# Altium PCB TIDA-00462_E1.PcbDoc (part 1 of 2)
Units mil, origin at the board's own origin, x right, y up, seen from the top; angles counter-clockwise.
Board outline 2300 x 2550 mil, 4 copper layers (Top Layer, MidLayer1 (GND), MidLayer2 (PWR), Bottom Layer), stack 79.8 mil thick; 106 components, 69 nets, 311 pads, 76 vias.
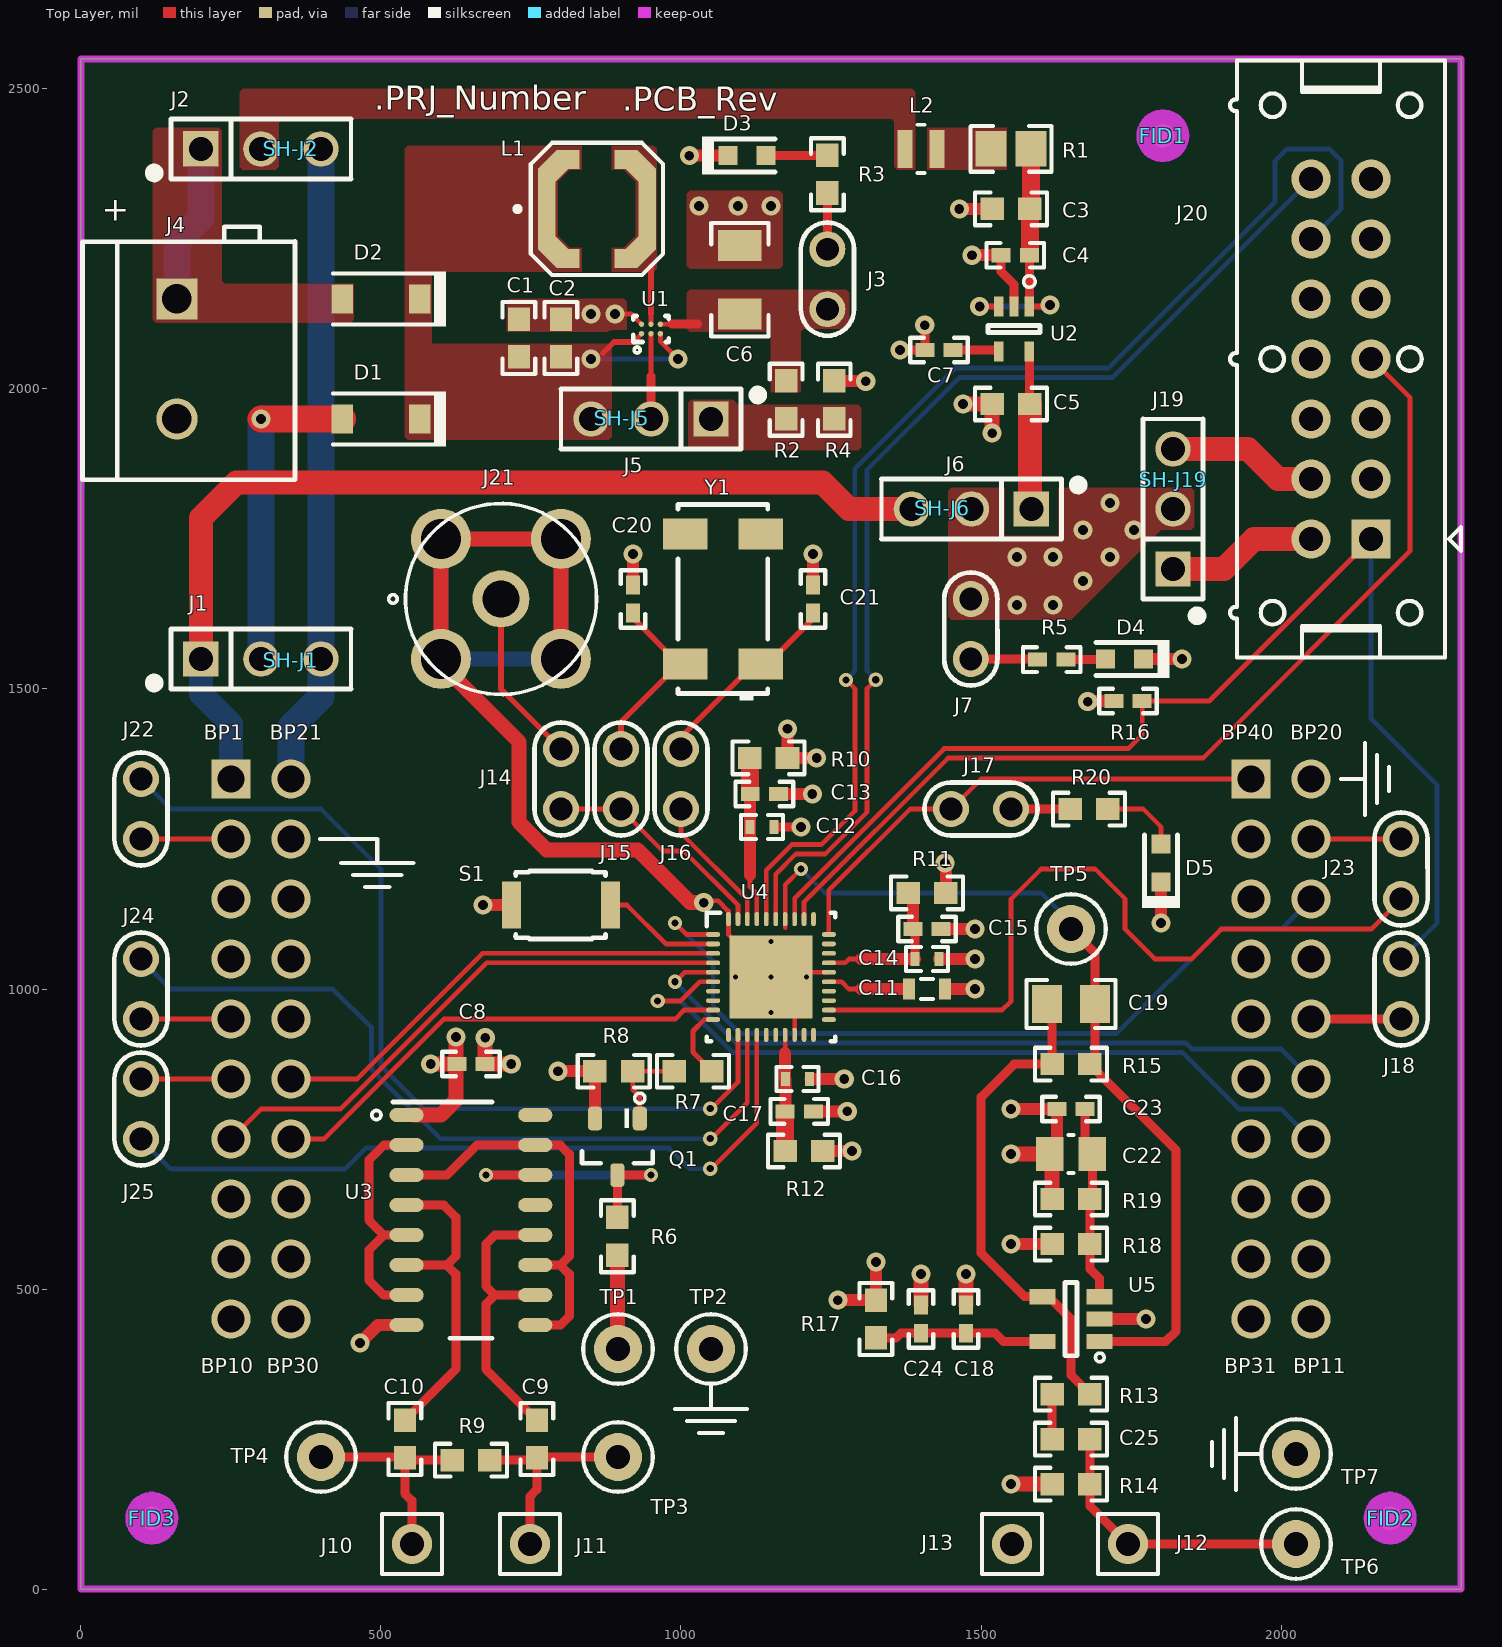
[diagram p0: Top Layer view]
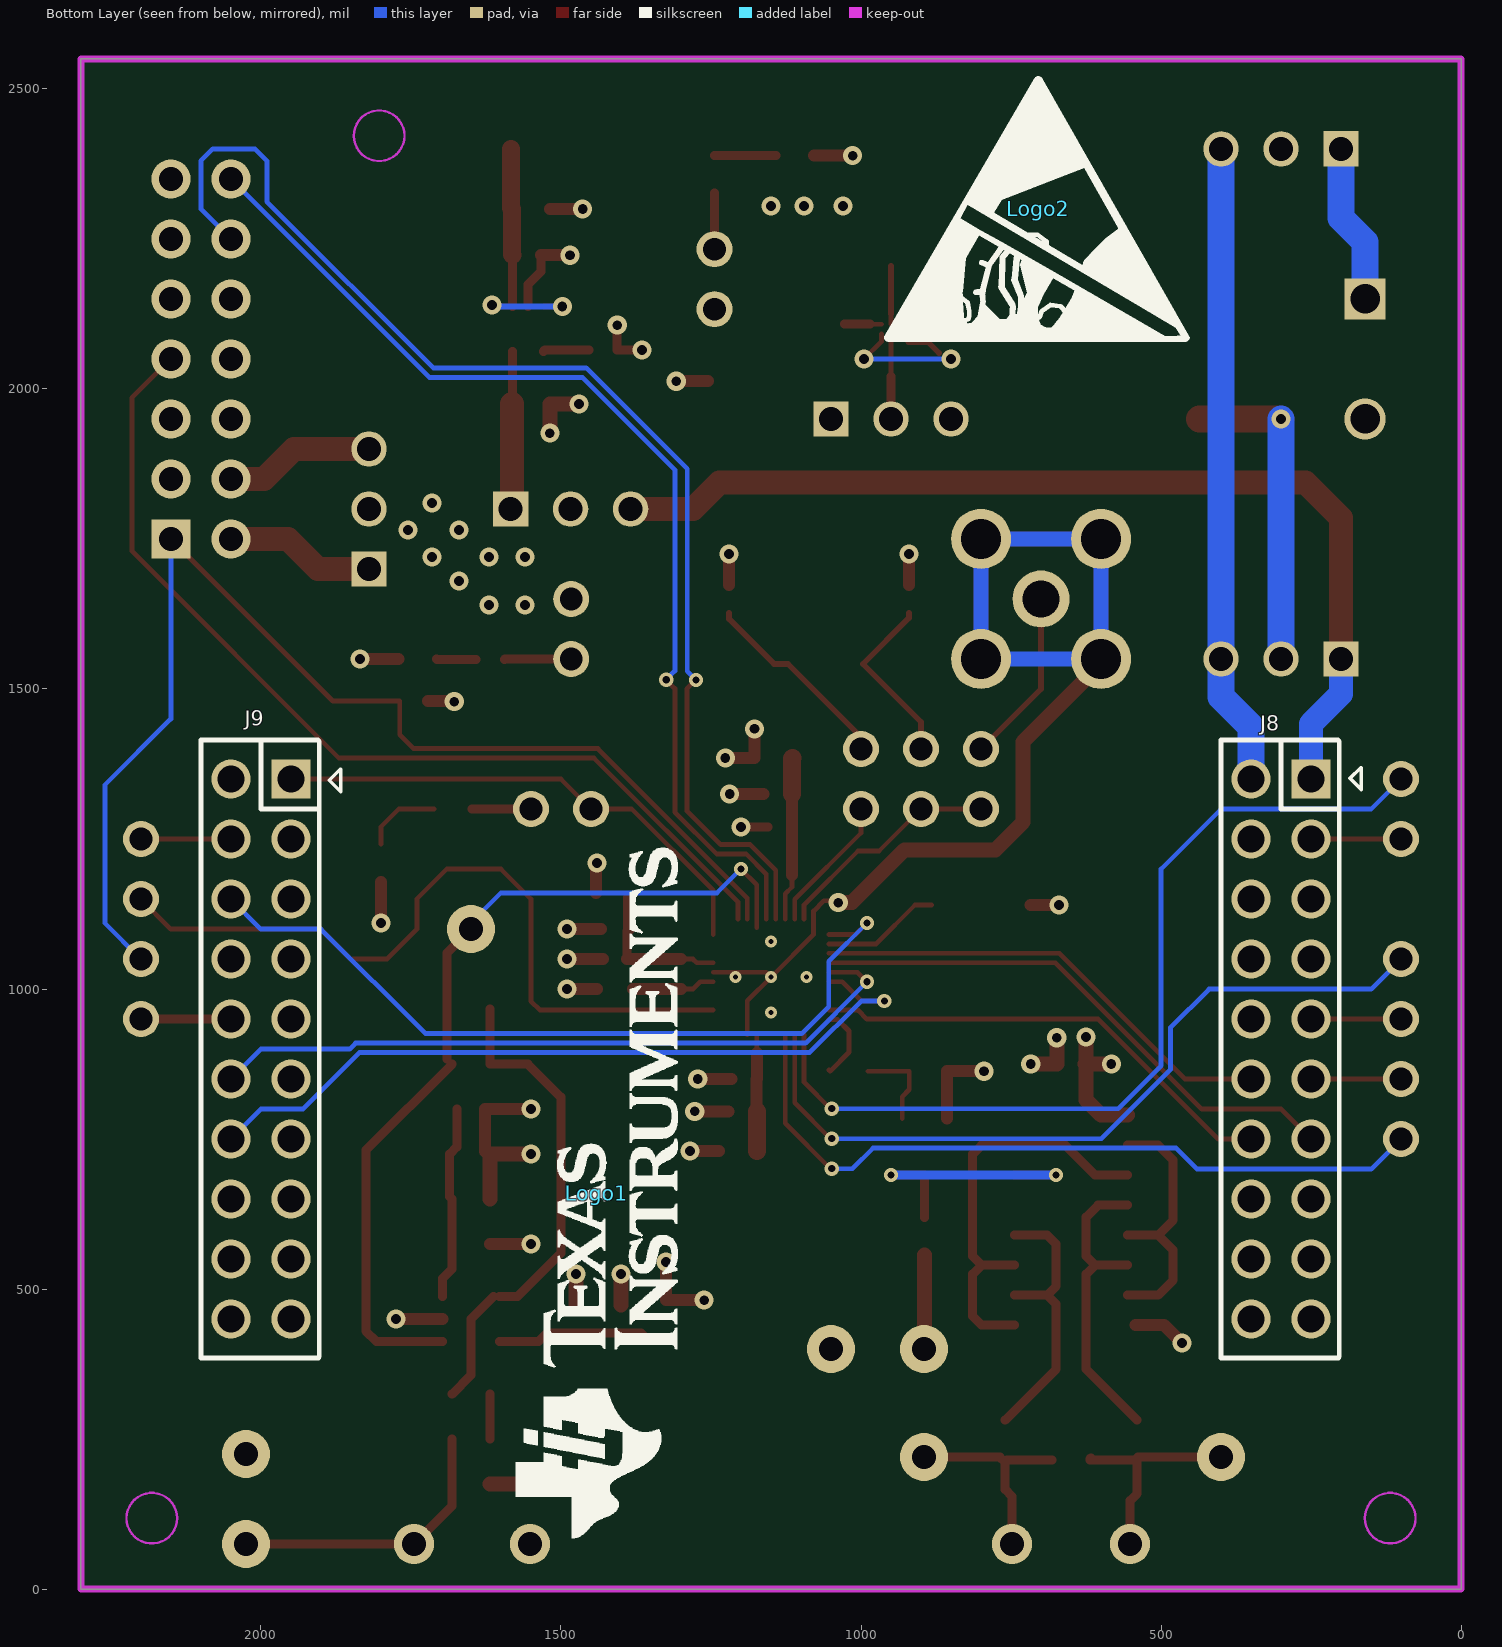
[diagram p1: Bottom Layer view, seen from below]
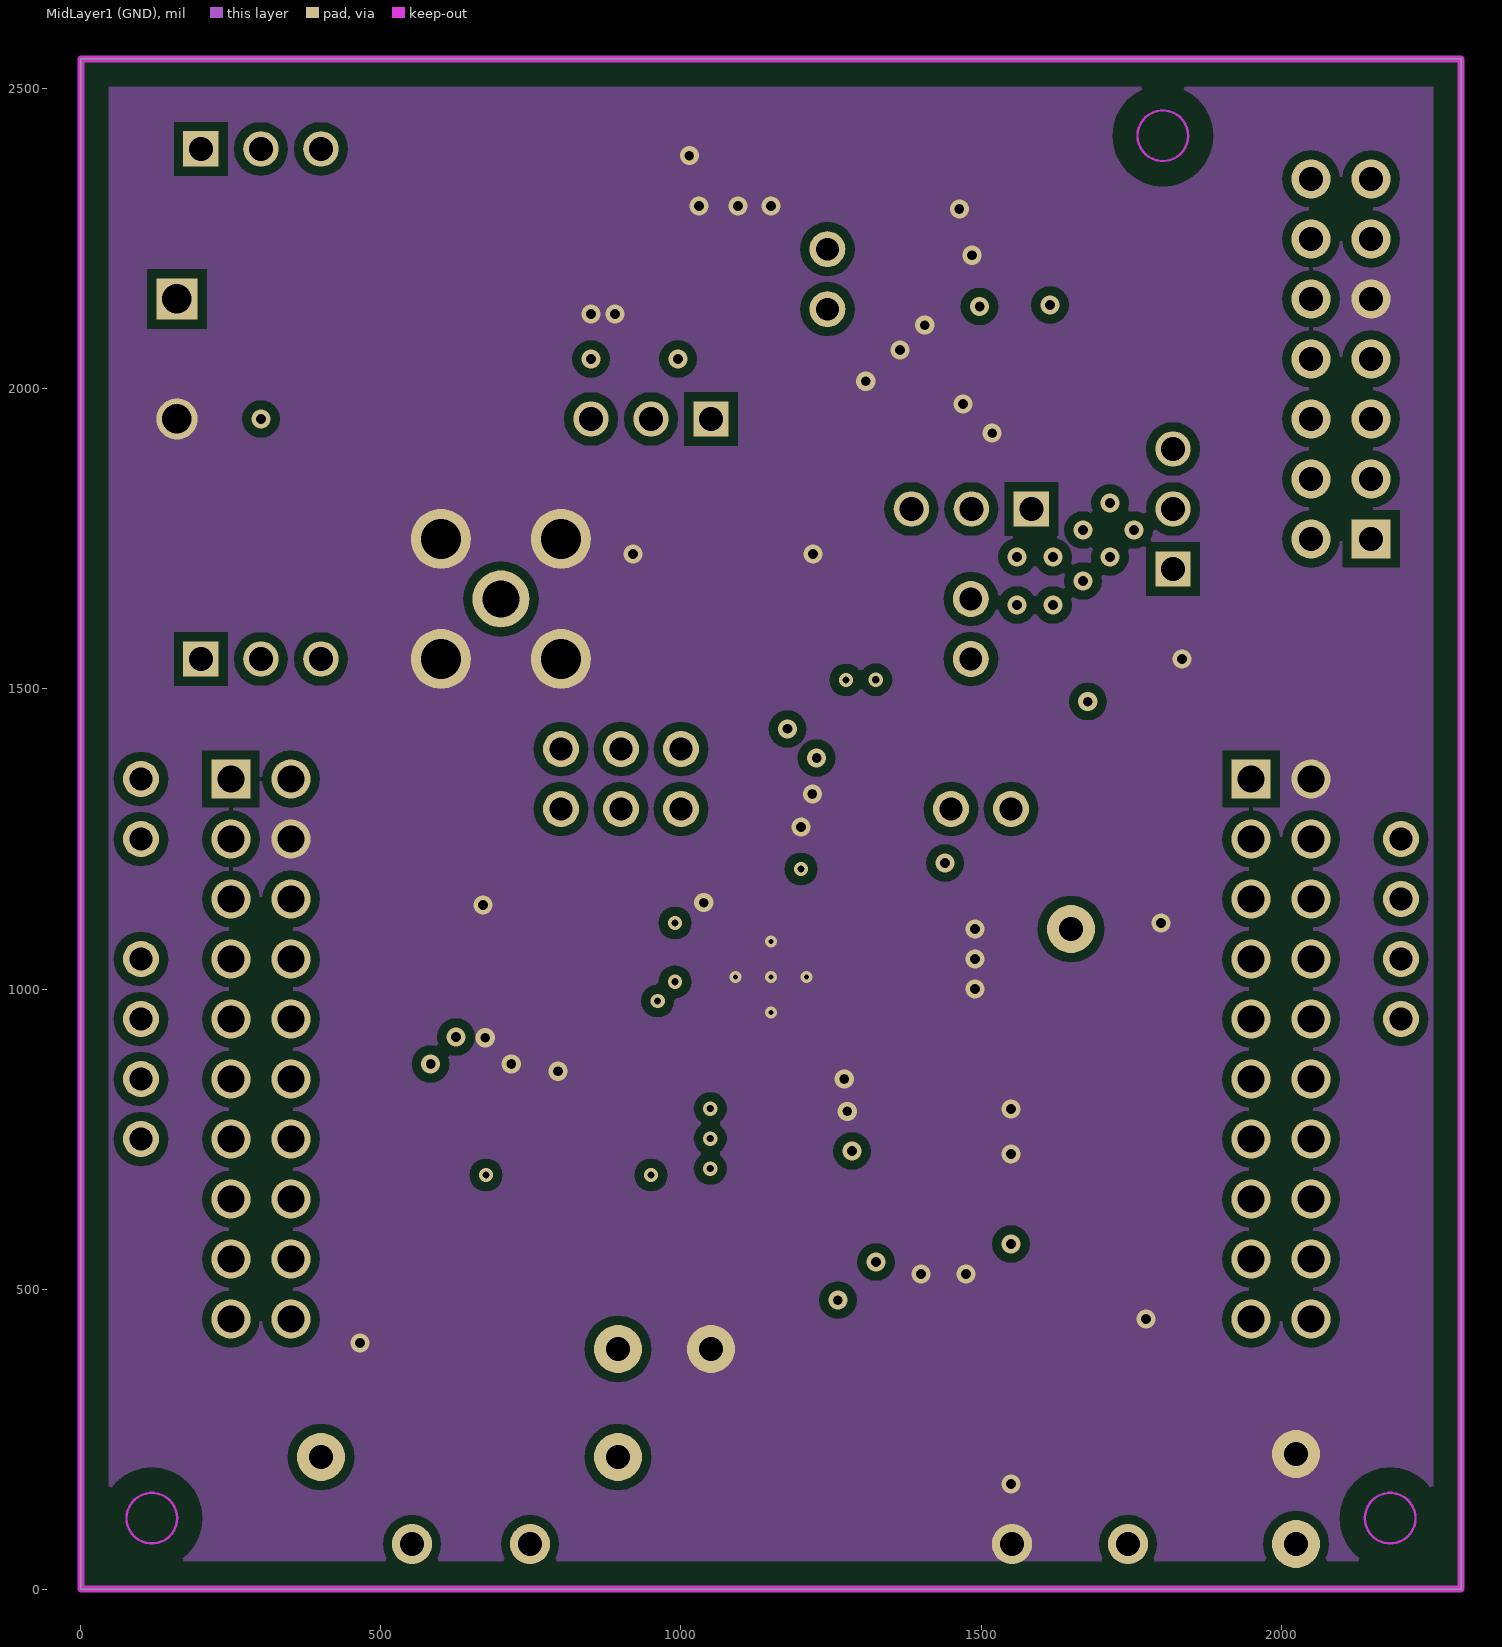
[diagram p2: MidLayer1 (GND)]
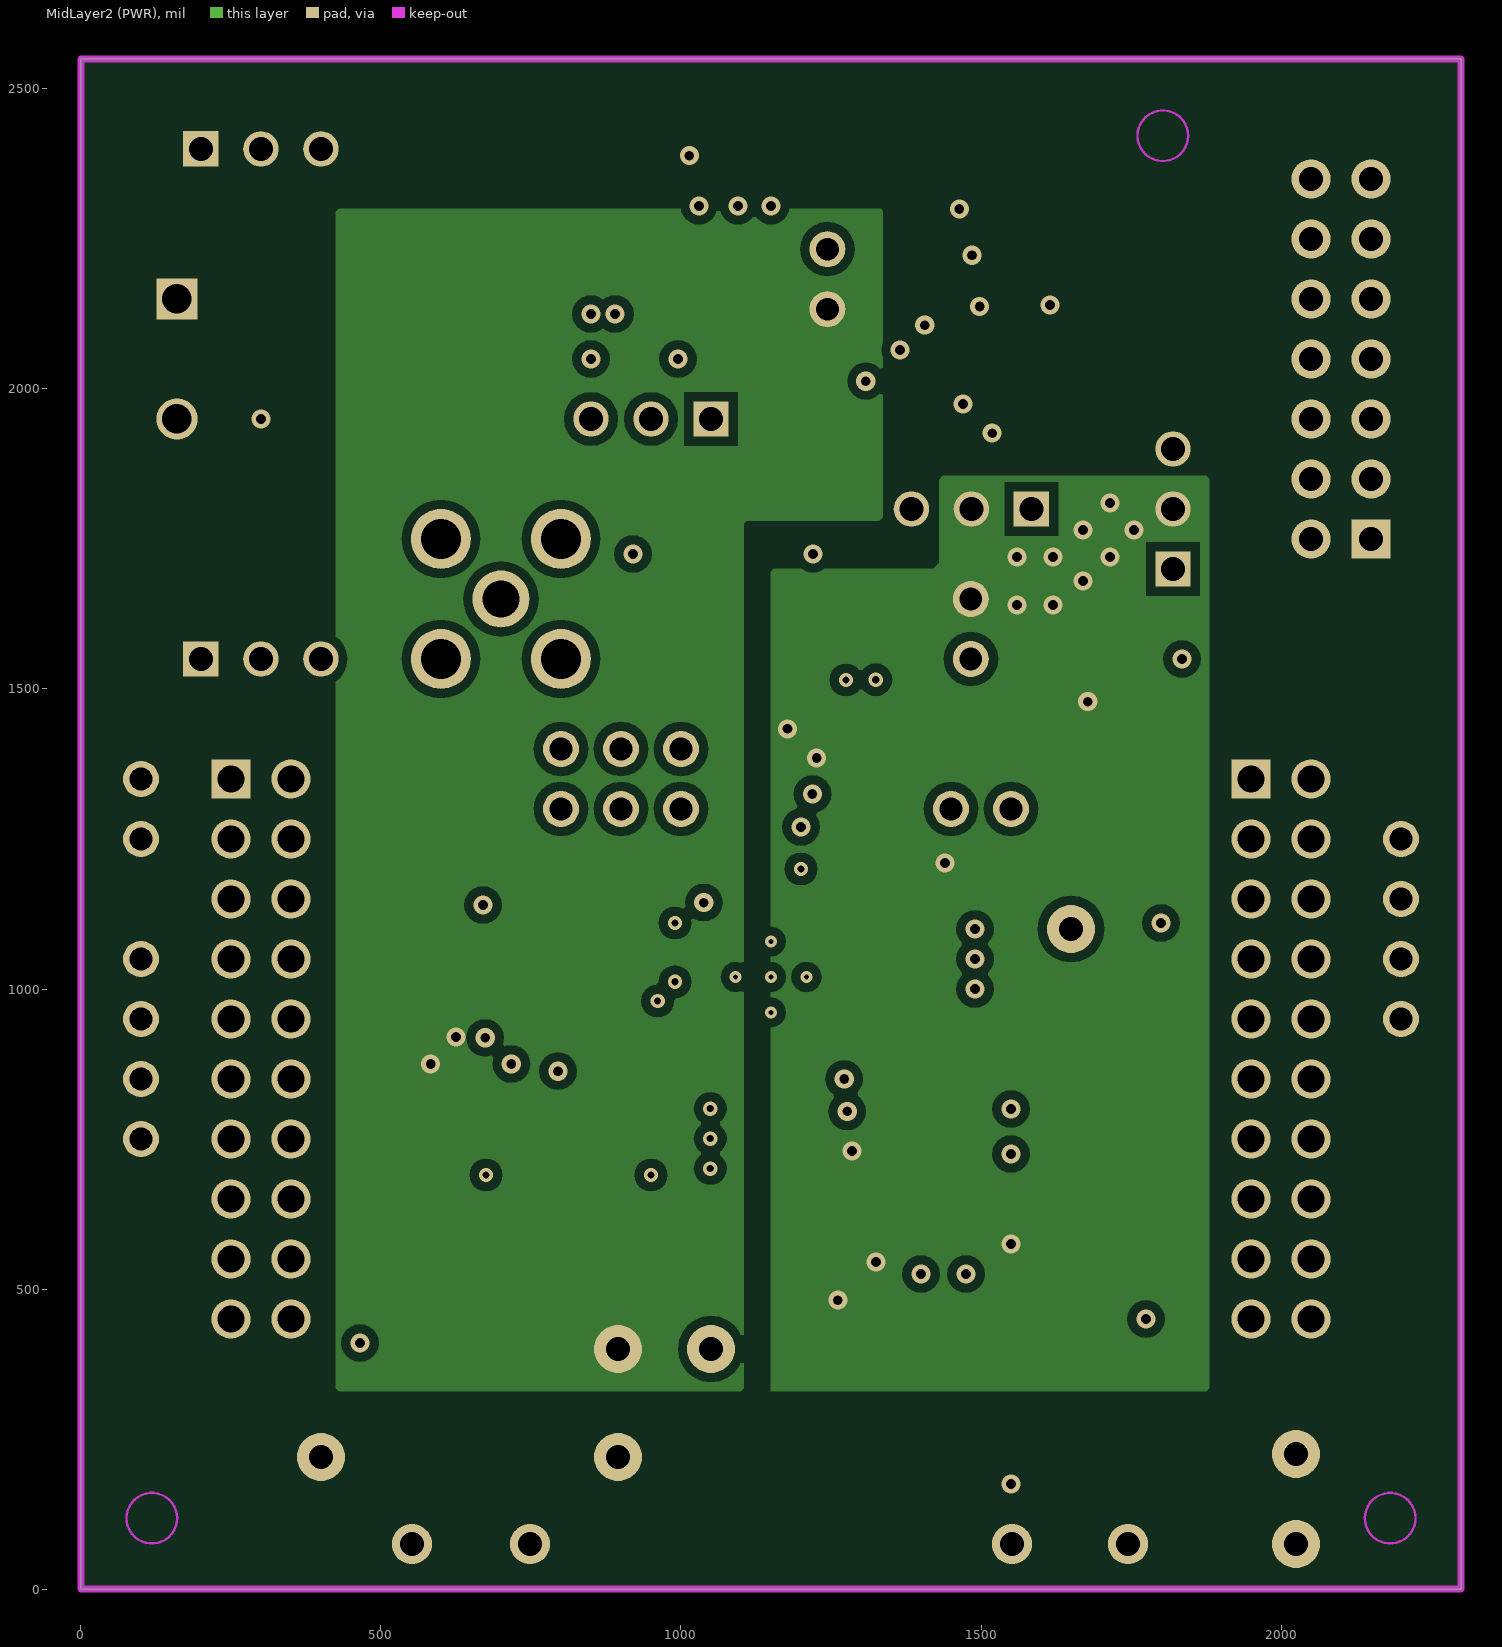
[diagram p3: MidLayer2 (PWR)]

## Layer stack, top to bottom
Top Solder: solder mask 0.4, Solder Resist, Dk 3.5
Top Layer: signal copper 1.4
Dielectric1: core 59.2, FR-4, Dk 4.8
MidLayer1 (GND): signal copper 1.4
Dielectric2: prepreg 5, Dk 4.2
MidLayer2 (PWR): signal copper 1.4
Dielectric3: core 10, Dk 4.2
Bottom Layer: signal copper 1.4
Bottom Solder: solder mask 0.4, Solder Resist, Dk 3.5

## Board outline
0,0 0,2550 2300,2550 2300,0 0,0

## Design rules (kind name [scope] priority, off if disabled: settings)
AcuteAngle [All] p1: minimum=4.50000000000000E+0001 checktracksonly=TRUE
AssemblyTestPointUsage [All] p1: valid=2
Clearance Clearance_U1 [InPadClass('u1_pad')] p1: gap=6.69
Clearance "Clearance_poly _poly" [InPolygon vs InPolygon] p2: gap=20
Clearance "VIA to SMD" [IsVia vs InAnyComponent] p3: gap=8
Clearance Clearance_BoardEdge_MountingHoles [OnCopper and InComponentClass('Mounting Holes') vs IsKeepOut] p4: gap=40
Clearance Clearance_BoardEdge_Poly [OnCopper and InPoly vs IsKeepOut] p5: gap=40
Clearance Clearance_Poly [InPolygon] p6: gap=15
Clearance [All] p7: gap=7.87
ComponentClearance ComponentClearance_MountingHoles_FiducialMarks [InComponentClass('Mounting Holes') vs InComponentClass('FiducialMark')] p1: gap=40 collisioncheckmode=3 verticalgap=10 showdistances=FALSE
ComponentClearance ComponentClearance_Shunt [InComponentClass('Header') vs InComponentClass('Shunt')] p2: gap=0 collisioncheckmode=3 verticalgap=0 showdistances=FALSE
ComponentClearance ComponentClearance_Logo [InComponentClass('Logo')] p3: gap=35 collisioncheckmode=3 verticalgap=10 showdistances=FALSE
ComponentClearance ComponentClearance_ScrewToNut [(HasFootprint('NY PMS 440 0025 PH')) vs (HasFootprint('Keystone_1902C'))] p4: gap=5 collisioncheckmode=3 verticalgap=10 showdistances=FALSE
ComponentClearance ComponentClearance_MountingHoles [InComponentClass('Mounting Holes')] p5: gap=250 collisioncheckmode=3 verticalgap=100000 showdistances=FALSE
ComponentClearance ComponentClearance_SmallPassives [HasFootprint('0201*') or HasFootprint('0402*') or HasFootprint('0508') or HasFootprint('0603*') or HasFootprint('0612') or HasFootprint('0805*') or HasFootprint('0815*') or HasFootprint('0830*') or HasFootprint('1206*') or HasFootprint('1210*') or HasFootprint('1808*') or HasFootprint('1812*') or HasFootprint('1825*') or HasFootprint('2010*') or HasFootprint('2220*') or HasFootprint('2225*') or HasFootprint('2512*') or HasFootprint('2728*') or HasFootprint('3518*') vs HasFootprint('0201*') or HasFootprint('0402*') or HasFootprint('0508') or HasFootprint('0603*') or HasFootprint('0612') or HasFootprint('0805*') or HasFootprint('0815*') or HasFootprint('0830*') or HasFootprint('1206*') or HasFootprint('1210*') or HasFootprint('1808*') or HasFootprint('1812*') or HasFootprint('1825*') or HasFootprint('2010*') or HasFootprint('2220*') or HasFootprint('2225*') or HasFootprint('2512*') or HasFootprint('2728*') or HasFootprint('3518*')] p6: gap=20 collisioncheckmode=3 verticalgap=10 showdistances=FALSE
ComponentClearance ComponentClearance_THtoSMT [IsThruComponent vs IsSMTComponent] p7: gap=50 collisioncheckmode=3 verticalgap=30 showdistances=FALSE
ComponentClearance ComponentClearance_THtoTH [IsThruComponent vs IsThruComponent] p8: gap=118.11 collisioncheckmode=3 verticalgap=30 showdistances=FALSE
ComponentClearance [All] p9: gap=30 collisioncheckmode=3 verticalgap=10 showdistances=FALSE
DiffPairsRouting DiffPair_DP_DMDiffPairsRouting [InDifferentialPair ('MSP_DP_DM_DIFF')] p1: maxlimit=8 minlimit=8 mostfreqgap=8 toplayer_minwidth=15 toplayer_maxwidth=15 toplayer_prefwidth=15 midlayer1_minwidth=15 midlayer1_maxwidth=15 midlayer1_prefwidth=15 midlayer2_minwidth=15 midlayer2_maxwidth=15 midlayer2_prefwidth=15 bottomlayer_minwidth=15 bottomlayer_maxwidth=15 bottomlayer_prefwidth=15 maxuncoupledlength=500
DiffPairsRouting DiffPair_MSP_DP_DMDiffPairsRouting [InDifferentialPair ('MSP_DP_DM_DIFF')] p2: maxlimit=8 minlimit=8 mostfreqgap=8 toplayer_minwidth=15 toplayer_maxwidth=15 toplayer_prefwidth=15 midlayer1_minwidth=15 midlayer1_maxwidth=15 midlayer1_prefwidth=15 midlayer2_minwidth=15 midlayer2_maxwidth=15 midlayer2_prefwidth=15 bottomlayer_minwidth=15 bottomlayer_maxwidth=15 bottomlayer_prefwidth=15 maxuncoupledlength=500
DiffPairsRouting [All] p3: maxlimit=8 minlimit=8 mostfreqgap=8 toplayer_minwidth=15 toplayer_maxwidth=15 toplayer_prefwidth=15 midlayer1_minwidth=15 midlayer1_maxwidth=15 midlayer1_prefwidth=15 midlayer2_minwidth=15 midlayer2_maxwidth=15 midlayer2_prefwidth=15 bottomlayer_minwidth=15 bottomlayer_maxwidth=15 bottomlayer_prefwidth=15 maxuncoupledlength=1000
FabricationTestPointUsage TestPointUsage [All] p1: valid=2 allowmultiple=FALSE
FabricationTestpoint Testpoint [All] p1: side=3 testpointundercomponent=TRUE minsize=40 maxsize=100 preferedsize=60 minholesize=0 maxholesize=40 preferedholesize=32 testpointgrid=1 allowsidetop=TRUE allowsidebottom=TRUE usegrid=TRUE gridtolerance=0.01
FanoutControl Fanout_LCC [IsLCC] p1: bgadir=Out bgaviamode=Centered fanoutstyle=Auto fanoutdirection=Alternating viagrid=1 // Fanout_LCC (Default Rule)
FanoutControl Fanout_BGA [IsBGA] p2: bgadir=Out bgaviamode=Centered fanoutstyle=Auto fanoutdirection=Alternating viagrid=1 // Fanout_BGA (Default Rule)
FanoutControl Fanout_Default [All] p4: bgadir=Out bgaviamode=Centered fanoutstyle=Auto fanoutdirection=Alternating viagrid=1 // Fanout_Default (Default Rule)
FanoutControl Fanout_Small [(CompPinCount < 5)] p5: bgadir=Out bgaviamode=Centered fanoutstyle=Auto fanoutdirection=OutThenIn viagrid=1 // Fanout_Small (Default Rule)
HoleSize [All] p1: absolutevalues=TRUE maxlimit=251 minlimit=7.87 maxpercent=80.000 minpercent=20.000
MatchedLengths DiffPair_DP_DMMatchedLengths [InDifferentialPair ('MSP_DP_DM_DIFF')] p1: tolerance=200 checknetsindiffpair=TRUE checkdiffpairvsdiffpair=TRUE checkothers=TRUE
MatchedLengths DiffPair_MSP_DP_DMMatchedLengths [InDifferentialPair ('MSP_DP_DM_DIFF')] p2: tolerance=200 checknetsindiffpair=TRUE checkdiffpairvsdiffpair=TRUE checkothers=TRUE
MinimumAnnularRing MinimumAnnularRing_ThermalPadVias [IsVia and InAnyComponent] p1: minimumring=5.91
MinimumAnnularRing [All] p2: minimumring=6
MinimumSolderMaskSliver MinimumSolderMaskSliver_Logo [InComponentClass('Logo') vs InComponentClass('Logo')] p1: minsoldermaskwidth=0.7
MinimumSolderMaskSliver [All] p2: minsoldermaskwidth=2.5
PlaneConnect [All] p1: planeconnectstyle=Direct reliefexpansion=10 reliefentries=4 reliefconductorwidth=10 reliefairgap=10
PolygonConnect [All] p1: connectstyle=Direct reliefconductorwidth=10 reliefentries=4 polygonreliefangle="90 Angle" airgapwidth=10
RoutingVias RoutingVias_power [InNetClass('power')] p1: holewidth=16 width=32 viastyle="Through Hole" minholewidth=16 minwidth=32 maxholewidth=16 maxwidth=32
RoutingVias ThermalPadVias [IsVia and InAnyComponent] p2: holewidth=12 width=24 viastyle="Through Hole" minholewidth=7.87 minwidth=19.68 maxholewidth=16 maxwidth=32
RoutingVias [All] p3: holewidth=12 width=24 viastyle="Through Hole" minholewidth=12 minwidth=24 maxholewidth=12 maxwidth=24
SilkToSilkClearance SilkToSilkClearance_Pb-FreeLogo [(HasFootprint('Pb-Free_Overlay_Medium') OR HasFootprint('Pb-Free_Overlay_Small')) vs (HasFootprint('Pb-Free_Overlay_Medium') OR HasFootprint('Pb-Free_Overlay_Small'))] p1: silktosilkclearance=0
SilkToSilkClearance [All] p2: silktosilkclearance=5
SilkToSolderMaskClearance "Silk to Solder Mask Opening" [IsPad] p1: minsilkscreentomaskgap=1 clearancetoexposedcopper=TRUE
SolderMaskExpansion [All] p1: expansion=1.97
UnpouredPolygon [All] p1: allowunpoured=FALSE
Width Width_PWR [InNetClass('power')] p1: maxlimit=100 minlimit=7.87 preferedwidth=20
Width [All] p2: maxlimit=100 minlimit=7.87 preferedwidth=10 checkconnectedcopper=TRUE
15 further rules are at their usual default settings.

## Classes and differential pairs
pad class u1_pad: U1-A1 U1-A2 U1-B1 U1-B2 U1-C1 U1-C2
component class Shunt: SH-J1 SH-J2 SH-J5 SH-J6 SH-J19
component class Logo: Logo1
component class TIDA-00462_E1_TID_Hardware: FID1 FID2 FID3 Logo1 Logo2 ZZ1 ZZ2 ZZ3 ZZ4
component class FiducialMark: FID1 FID2 FID3
component class AssemblyNote: ZZ1 ZZ2 ZZ3 ZZ4
component class TIDA-00462_E1_Power_Supply: C1 C2 C3 C4 C5 C6 C7 D1 D2 D3 D4 J1 J2 J3 J4 J5 J6 J7 J8 J9 J18 J19 J20 J22 J23 J24 J25 L1 L2 R1 R2 R3 R4 R5 SH-J1 SH-J2 SH-J5 SH-J6 SH-J19 TP1 TP2 U1 U2
component class TIDA-00462_E1_MCU_US_TX_RX: C8 C9 C10 C11 C12 C13 C14 C15 C16 C17 C18 C19 C20 C21 C22 C23 C24 C25 D5 J10 J11 J12 J13 J14 J15 J16 J17 J21 Q1 R6 R7 R8 R9 R10 R11 R12 R13 R14 R15 R16 R17 R18 R19 R20 S1 TP3 TP4 TP5 TP6 TP7 U3 U4 U5 Y1

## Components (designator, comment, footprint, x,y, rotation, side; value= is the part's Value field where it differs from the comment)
C1 "C1608X7R1C105K" 0603 730,2085 r90 top
C2 "C0603C104M4RACTU" 0603 800,2085 r90 top
C3 "GRM188R71E105KA12D" 0603 1550,2300 r180 top
C4 "C1005X7R1H104K050BB" 0402 1557,2223 r180 top
C5 "GRM188R71E105KA12D" 0603 1550,1975 r180 top
C6 "GMK316AB7106KL" 1206 1098,2182 r90 top
C7 "C1005X7R1C103K" 0402 1430,2065 r180 top
C8 "C1005X7R1H104K050BB" 0402 650,875 r0 top
C9 "C1608X7R1H224K080AB" 0603 760,250 r90 top
C10 "C1608X7R1H224K080AB" 0603 540,250 r90 top
C11 "GRM188R70J474KA01D" 0603S 1410,1000 r0 top
C12 "GRM155R70J104KA01D" 0402S 1135,1270 r0 top
C13 "CL05A106MQ5NUNC" 0402 1139,1325 r0 top
C14 "GRM155R70J104KA01D" 0402S 1410,1050 r0 top
C15 "CL05A106MQ5NUNC" 0402 1410,1100 r0 top
C16 "GRM155R70J104KA01D" 0402S 1194,850 r0 top
C17 "CL05A106MQ5NUNC" 0402 1197,796 r0 top
C18 "C1005X7R1H104K050BB" 0402 1475,450 r90 top
C19 "CC0805DRNP09BN7R0" 0805_HV 1650,975 r0 top
C20 "C1005C0G1H220J050BA" 0402 920,1650 r90 top
C21 "C1005C0G1H220J050BA" 0402 1220,1650 r90 top
C22 "885012207026" 0805_145 1650,725 r180 top
C23 "C1005X7R1H104K050BB" 0402 1650,800 r180 top
C24 "CL05A106MQ5NUNC" 0402 1400,450 r90 top
C25 "GRM188R71C103KA01D" 0603 1650,250 r180 top
D1 "MBR0540T1G" SOD-123 500,1950 r180 top
D2 "MBR0540T1G" SOD-123 500,2150 r180 top
D3 "150060VS75000" WL-SMCW_GREEN 1110,2389 r0 top
D4 "150060VS75000" WL-SMCW_GREEN 1739,1550 r180 top
D5 "150060SS75000" WL-SMCW_RED 1800,1210 r90 top
FID1 "Fiducial" Fiducial10-20 1803,2422 r0 top
FID2 "Fiducial" Fiducial10-20 2181.89,118.11 r0 top
FID3 "Fiducial" Fiducial10-20 118.11,118.11 r0 top
J1 "PEC03SAAN" CONN_PEC03SAAN 300,1550 r0 top
J2 "PEC03SAAN" CONN_PEC03SAAN 300,2400 r0 top
J3 "923345-01-C" 3M_923345-01-C 1244,2183 r270 top
J4 "ED120/2DS" CONN_ED120-2DS 160,2050 r180 top
J5 "PEC03SAAN" CONN_PEC03SAAN 950,1950 r180 top
J6 "PEC03SAAN" CONN_PEC03SAAN 1484,1800 r180 top
J7 "923345-01-C" 3M_923345-01-C 1483,1600 r90 top
J8 "SSW-110-23-F-D" CONN_SSW-110-23-F-D 300,900 r90 bottom locked
J9 "SSW-110-23-F-D" CONN_SSW-110-23-F-D 2000,900 r90 bottom locked
J10 "TSW-101-17-T-S" Samtec_TSW-101-17-T-S 551.57,75 r90 top
J11 "TSW-101-17-T-S" Samtec_TSW-101-17-T-S 748.43,75 r0 top
J12 "TSW-101-17-T-S" Samtec_TSW-101-17-T-S 1745,75 r90 top
J13 "TSW-101-17-T-S" Samtec_TSW-101-17-T-S 1551.57,75 r0 top
J14 "923345-01-C" 3M_923345-01-C 800,1350 r270 top
J15 "923345-01-C" 3M_923345-01-C 900,1350 r270 top
J16 "923345-01-C" 3M_923345-01-C 1000,1350 r270 top
J17 "923345-01-C" 3M_923345-01-C 1500,1300 r0 top
J18 "923345-01-C" 3M_923345-01-C 2200,1000 r270 top
J19 "PEC03SAAN" CONN_PEC03SAAN 1820,1800 r90 top
J20 "SBH11-PBPC-D07-ST-BK" CONN_SBH11-PBPC-D07-ST-BK 2100,2050 r90 top
J21 "142-0701-201" Johnson_142-0701-20x 700,1650 r0 top
J22 "923345-01-C" 3M_923345-01-C 100,1300 r90 top
J23 "923345-01-C" 3M_923345-01-C 2200,1200 r90 top
J24 "923345-01-C" 3M_923345-01-C 100,1000 r90 top
J25 "923345-01-C" 3M_923345-01-C 100,800 r270 top
L1 "LPS5030-103MLB" LPS5030 860,2300 r0 top
L2 "VLS201610ET-100M" VLS201610 1400,2400 r0 top
Logo1 "Texas Instruments" TI_Stacked_Overlay_Medium_Vertical 1440,660 r180 bottom
Logo2 "ESD Susceptible" ESD_Overlay_Large 705,2300 r180 bottom
Q1 "MMBT3904LT1G" SOT-23 894,737 r270 top
R1 "ERJ-6GEYJ1R6V" 0805 1550,2400 r0 top
R2 "RC0603FR-07560KL" 0603 1175.32,1982 r90 top
R3 "CRCW06032K40JNEA" 0603 1244,2358 r270 top
R4 "RT0603DRE0754K2L" 0603 1255.32,1982 r270 top
R5 "CRCW04021K00JNED" 0402 1618,1549 r0 top
R6 "ERJ-3EKF1002V" 0603 894,588 r270 top
R7 "ERJ-3EKF1002V" 0603 1020,863 r180 top
R8 "ERJ-3EKF1002V" 0603 888,863 r180 top
R9 "RC0603FR-07100KL" 0603 650,215 r0 top
R10 "CRCW060310R0FKEA" 0603 1146,1385 r0 top
R11 "CRCW060310R0FKEA" 0603 1410,1160 r0 top
R12 "CRCW060310R0FKEA" 0603 1205,730 r0 top
R13 "ERJ-3EKF1501V" 0603 1650,325 r180 top
R14 "CRCW06033K90JNEA" 0603 1650,175 r0 top
R15 "CRCW0603499KFKEA" 0603 1650,875 r180 top
R16 "CRCW040247K0JNED" 0402 1745,1480 r180 top
R17 "CRCW060310R0FKEA" 0603 1325,450 r90 top
R18 "CRCW06031M00FKEA" 0603 1650,575 r180 top
R19 "CRCW06031M00FKEA" 0603 1650,650 r0 top
R20 "CRCW0603560RJNEA" 0603 1680,1300 r180 top
S1 "SKRKAEE010" SW_SKRKAEE010 800,1140 r180 top
SH-J1 "969102-0000-DA" SNT-100-BK-G 350,1548 r180 top
SH-J2 "969102-0000-DA" SNT-100-BK-G 350,2400 r180 top
SH-J5 "969102-0000-DA" SNT-100-BK-G 901,1951 r180 top
SH-J6 "969102-0000-DA" SNT-100-BK-G 1435,1801 r0 top
SH-J19 "969102-0000-DA" SNT-100-BK-G 1820,1849 r90 top
TP1 "5002" Keystone5002 895,400 r0 top
TP2 "5001" Keystone5001 1050,400 r0 top
TP3 "5000" Keystone5000 895,220 r0 top
TP4 "5000" Keystone5000 400,220 r0 top
TP5 "5000" Keystone5000 1650,1100 r0 top
TP6 "5000" Keystone5000 2025,75 r90 top
TP7 "5001" Keystone5001 2025,225 r90 top
U1 "TPS610461YFF" YFF0006AAAA 950,2100 r90 top
U2 "TPS71733DCKR" DCK0005A_N 1555,2100 r270 top
U3 "CD4049UBDR" D0016A_N 650,615 r0 top
U4 "MSP430F5172IRSB" RSB0040B 1150,1020 r0 top
U5 "LMP7715MF" DBV0005A_N 1650,450 r180 top
Y1 "CM250C40000AZFT" CFM_CM250C 1070,1650 r180 top
ZZ1 "This Assembly Note is for PCB labels only" AssemblyNoteLabel 185,3938 r0 top
ZZ2 "These assemblies are ESD sensitive, ESD precautions shall be observed." AssemblyNote 185,3829.11 r0 top
ZZ3 "These assemblies must be clean and free from flux and all contaminants. Use of no clean flux is not acceptable." AssemblyNote 185,3740.56 r0 top
ZZ4 "These assemblies must comply with workmanship standards IPC-A-610 Class 2, unless otherwise specified." AssemblyNote 185,3652 r0 top

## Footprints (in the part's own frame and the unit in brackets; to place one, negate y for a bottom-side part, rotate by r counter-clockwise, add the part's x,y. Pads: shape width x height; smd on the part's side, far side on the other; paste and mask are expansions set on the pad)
3M_923345-01-C [mil] "Wire Jumper"
  round 60 hole 38: 1(-50,0) 2(50,0)
  silkscreen extent -94,-44 94,44, body extent -63,-13 63,13, height 74
0402 [mm] "0402 from SM-752 data"
  rect 0.8x0.6 smd: 1(-0.6,0) 2(0.6,0)
  silkscreen extent -1.22,-0.52 1.22,0.52, body extent -0.55,-0.3 0.55,0.3, height 0.6
0402S [mil] "Based on C0402S footprint from PADS legacy"
  rect 15x24 smd: 1(-20,0) 2(20,0)
  silkscreen extent -35,-20 35,20, body extent -22,-12 22,12, height 24
0603 [mm] "0603 from SM-752 data"
  rect 1x0.95 smd: 1(-0.8,0) 2(0.8,0)
  silkscreen extent -1.52,-0.69 1.52,0.69, body extent -0.87,-0.47 0.87,0.47, height 0.85
0603S [mil]
  rect 20x35 smd: 1(-30,0) 2(30,0)
  silkscreen extent -10,-17 10,17, body extent -34,-19 34,19, height 33
0805 [mm] "0805 from SM-752 data"
  rect 1.3x1.5 smd: 1(-0.85,0) 2(0.85,0)
  silkscreen extent -1.72,-0.97 1.72,0.97, body extent -1.1,-0.72 1.1,0.72, height 1.1
0805_145 [mm] "0805 / 1.45mm height"
  rect 1.15x1.45 smd: 1(-0.9,0) 2(0.9,0)
  silkscreen extent -0.1,-0.8 0.1,0.8, body extent -1.1,-0.72 1.1,0.72, height 1.45
0805_HV [mil] "0805 with 30mil clearance between pads"
  rect 50x63 smd: 1(-40,0) 2(40,0)
  silkscreen extent -74,-40 74,40, body extent -43,-29 43,29, height 57
1206 [mm] "1206 from SM-752 data"
  rect 1.3x1.85 smd: 1(-1.45,0) 2(1.45,0)
  silkscreen extent -2.4,-1.21 2.4,1.21, body extent -1.7,-0.9 1.7,0.9, height 1.35
AssemblyNote [mil] "Assembly Note"
AssemblyNoteLabel [mil] "Assembly Note for PCB Labels"
CFM_CM250C [mm] "SMD, 4-Leads, Body 7.9x3.7mm"
  rect 1.9x1.3 smd: 1(-1.6,2.75) 2(-1.6,-2.75) 3(1.6,-2.75) 4(1.6,2.75)
  silkscreen extent -1.9,-4 1.9,4.3, body extent -1.9,-4 1.9,4, height 2.51
CONN_ED120-2DS [mm] "ONSHORE"
  rect 1.75x1.75 hole 1.25: 1(0,-2.54)
  round 1.75 hole 1.25: 2(0,2.54)
  silkscreen extent -5,-5.6 4,5.12, body extent -5,-5.6 4.15,5.12, height 13.1
CONN_PEC03SAAN [mm] "SULLINS"
  rect 1.5x1.5 hole 1.016: 1(-2.54,0)
  round 1.5 hole 1.016: 2(0,0) 3(2.54,0)
  silkscreen extent -4.72,-1.27 3.81,1.27, body extent -3.84,-1.3 3.84,1.3, height 8.38
CONN_SBH11-PBPC-D07-ST-BK [mm] "Sullins recommended land pattern"
  rect 1.65x1.65 hole 1.016 mask+0.05: 1(-7.62,-1.27)
  round 1.65 hole 1.016 mask+0.05: 2(-7.62,1.27) 3(-5.08,-1.27) 4(-5.08,1.27) 5(-2.54,-1.27) 6(-2.54,1.27) 7(0,-1.27) 8(0,1.27) 9(2.54,-1.27) 10(2.54,1.27) 11(5.08,-1.27) 12(5.08,1.27) 13(7.62,-1.27) 14(7.62,1.27)
  silkscreen extent -12.64,-5.08 12.64,4.7, body extent -12.64,-4.4 12.64,4.7, height 9.12
CONN_SSW-110-23-F-D [mm] "SAMTEC"
  rect 1.65x1.65 hole 1.15: 1(11.43,-1.27)
  round 1.65 hole 1.15: 2(11.43,1.27) 3(8.89,-1.27) 4(8.89,1.27) 5(6.35,-1.27) 6(6.35,1.27) 7(3.81,-1.27) 8(3.81,1.27) 9(1.27,-1.27) 10(1.27,1.27) 11(-1.27,-1.27) 12(-1.27,1.27) 13(-3.81,-1.27) 14(-3.81,1.27) 15(-6.35,-1.27) 16(-6.35,1.27) 17(-8.89,-1.27) 18(-8.89,1.27) 19(-11.43,-1.27) 20(-11.43,1.27)
  silkscreen extent -13.08,-2.46 13.08,2.54, body extent -13,-2.51 13,2.54, height 8.59
D0016A_N [mm] "SOIC, 16-Leads, Body 9.9x3.9mm, Pitch 1.27mm, IPC Medium Density"
  oval 1.45x0.6 smd: 1(-2.725,4.445) 2(-2.725,3.175) 3(-2.725,1.905) 4(-2.725,0.635) 5(-2.725,-0.635) 6(-2.725,-1.905) 7(-2.725,-3.175) 8(-2.725,-4.445) 9(2.725,-4.445) 10(2.725,-3.175) 11(2.725,-1.905) 12(2.725,-0.635) 13(2.725,0.635) 14(2.725,1.905) 15(2.725,3.175) 16(2.725,4.445)
  silkscreen extent -3.3,-5 0.9,5, body extent -3,-4.95 3,4.95, height 1.6
DBV0005A_N [mm] "SOT23, 5-Leads, Body 2.9x1.6mm, Pitch 0.95mm, Lead Span 2.8mm, IPC Medium Density"
  rect 1.1x0.65 smd: 1(-1.2,0.95) 2(-1.2,0) 3(-1.2,-0.95) 4(1.2,-0.95) 5(1.2,0.95)
  silkscreen extent -0.25,-1.55 0.25,1.55, body extent -1.42,-1.46 1.42,1.46, height 1.08
DCK0005A_N [mm] "SOT353, 5-Leads, Body 2x1.3mm, Pitch 0.65mm, Lead Span 2.1mm, IPC Medium Density"
  rect 0.85x0.4 smd: 1(-0.95,0.65) 2(-0.95,0) 3(-0.95,-0.65) 4(0.95,-0.65) 5(0.95,0.65)
  silkscreen extent -0.15,-1.1 0.15,1.1, body extent -1.14,-1 1.14,1, height 0.94
ESD_Overlay_Large [mil]
  silkscreen extent -254,-219 250,219
Fiducial10-20 [mm]
  round 1 smd mask+0.5: 1(0,0)
  Top Layer keep-out circle w1.178: c0,0 r0.5
Johnson_142-0701-20x [mil] "Johnson Components recommended land pattern"
  round 95 hole 62: 1(0,0)
  round 100 hole 67: 2(100,100) 3(100,-100) 4(-100,-100) 5(-100,100)
  body extent -156,-156 156,156, height 375
Keystone5000 [mil] "For Keystone 500x miniature loop terminals"
  round 80 hole 40: 1(0,0)
  silkscreen extent -58,-58 58,58, body extent -49,-49 49,49, height 182
Keystone5001 [mil] "For Keystone 500x miniature loop terminals"
  round 80 hole 40: 1(0,0)
  silkscreen extent -58,-58 58,58, body extent -49,-49 49,49, height 182
Keystone5002 [mil] "For Keystone 500x miniature loop terminals"
  round 80 hole 40: 1(0,0)
  silkscreen extent -58,-58 58,58, body extent -49,-49 49,49, height 182
LPS5030 [mm] "Coilcraft recommended land pattern.  Document 581-2, rev 10/06/08"
  rect 0.75x3.4 smd: 1(-2.125,0) 2(2.125,0)
  rect 1.131x0.92 smd rot 135: 1(-1.776,-1.776) 2(1.776,1.776)
  rect 1.131x0.92 smd rot 45: 1(-1.776,1.776) 2(1.776,-1.776)
  rect 0.95x0.8 smd: 1(-1.225,-2.1) 1(-1.225,2.1) 2(1.225,-2.1) 2(1.225,2.1)
  silkscreen extent -3.45,-2.8 2.8,2.8, body extent -2.5,-2.5 2.5,2.5, height 3.02
RSB0040B [mm] "QFN, 40-Leads, Body 5x5mm, Pitch 0.4mm, Thermal Pad 3.5x3.5mm, TI Recommended"
  oval 0.6x0.2 smd: 1(-2.45,1.8) 2(-2.45,1.4) 3(-2.45,1) 4(-2.45,0.6) 5(-2.45,0.2) 6(-2.45,-0.2) 7(-2.45,-0.6) 8(-2.45,-1) 9(-2.45,-1.4) 10(-2.45,-1.8) 21(2.45,-1.8) 22(2.45,-1.4) 23(2.45,-1) 24(2.45,-0.6) 25(2.45,-0.2) 26(2.45,0.2) 27(2.45,0.6) 28(2.45,1) 29(2.45,1.4) 30(2.45,1.8)
  oval 0.2x0.6 smd: 11(-1.8,-2.45) 12(-1.4,-2.45) 13(-1,-2.45) 14(-0.6,-2.45) 15(-0.2,-2.45) 16(0.2,-2.45) 17(0.6,-2.45) 18(1,-2.45) 19(1.4,-2.45) 20(1.8,-2.45) 31(1.8,2.45) 32(1.4,2.45) 33(1,2.45) 34(0.6,2.45) 35(0.2,2.45) 36(-0.2,2.45) 37(-0.6,2.45) 38(-1,2.45) 39(-1.4,2.45) 40(-1.8,2.45)
  rect 3.5x3.5 smd paste-1.75: 41(0,0)
  silkscreen extent -2.72,-2.73 2.72,2.73, body extent -2.57,-2.57 2.58,2.58, height 0.81
Samtec_TSW-101-17-T-S [mm] "Samtec,CONN HEADER 1POS .100\" SNGL TIN"
  round 1.7 hole 1.02 mask+0.05: 1(0,0)
  silkscreen extent -1.27,-1.27 1.27,1.27, body extent -1.27,-1.27 1.27,1.27, height 18.29
SNT-100-BK-G [mil] "Samtec STEP model"
  round 1 on Mech3: 0(0,0)
  body extent -100,-50 100,50, height 344
SOD-123 [mm] "On Semi recommended land pattern"
  rect 0.915x1.22 smd: 1(-1.637,0) 2(1.637,0)
  silkscreen extent -2.74,-1.17 2.03,1.17, body extent -1.93,-0.9 1.93,0.9, height 1.35
SOT-23 [mm] "SOT23, 3-Leads, Body 2.9x1.3mm, Pitch 0.95mm, Lead Span 2.5mm, IPC Medium Density"
  rrect50% 1x0.6 smd: 1(-1.2,0.95) 2(-1.2,-0.95) 3(1.2,0)
  silkscreen extent -1.63,-1.5 0.7,1.5, body extent -1.16,-1.45 1.21,1.45, height 1
SW_SKRKAEE010 [mm] "Alps recommended land pattern"
  rect 0.8x2 smd: 1(-2.1,0) 2(2.1,0)
  silkscreen extent -1.9,-1.44 1.92,1.44, body extent -2.4,-1.45 2.4,1.45, height 1.96
TI_Stacked_Overlay_Medium_Vertical [mil]
  silkscreen extent -135,-576 135,576
VLS201610 [mm] "TDK"
  rect 0.65x1.6 smd: 1(-0.675,0) 2(0.675,0)
  silkscreen extent -0.15,-1.02 0.15,1.02, body extent -1.05,-0.85 1.05,0.85, height 0.95
WL-SMCW_GREEN [mm] "WURTH"
  rect 0.8x0.8 smd: 1(-0.8,0) 2(0.8,0)
  silkscreen extent -1.9,-0.8 1.2,0.8, body extent -0.85,-0.45 0.85,0.45, height 0.8
WL-SMCW_RED [mm] "WURTH"
  rect 0.8x0.8 smd: 1(-0.8,0) 2(0.8,0)
  silkscreen extent -1.9,-0.8 1.2,0.8, body extent -0.85,-0.45 0.85,0.45, height 0.8
YFF0006AAAA [mm] "DSBGA, 6-Leads, Body 0.8x1.2mm, Pitch 0.4mm"
  round 0.23 smd paste-0.13 mask+0.038: A1(-0.2,0.4) A2(0.2,0.4) B1(-0.2,0) B2(0.2,0) C1(-0.2,-0.4) C2(0.2,-0.4)
  silkscreen extent -0.55,-0.75 0.55,0.75, body extent -0.41,-0.61 0.41,0.61, height 0.63

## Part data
C1: "CAP, CERM, 1 µF, 16 V, +/- 10%, X7R, 0603"
C2: "CAP, CERM, 0.1 µF, 16 V, +/- 20%, X7R, 0603"
C3 C5: "CAP, CERM, 1 µF, 25 V, +/- 10%, X7R, 0603"
C4 C8 C18 C23: "CAP, CERM, 0.1 µF, 50 V, +/- 10%, X7R, 0402"
C6: "CAP, CERM, 10 µF, 35 V, +/- 10%, X7R, 1206"
C7: "CAP, CERM, 0.01 µF, 16 V, +/- 10%, X7R, 0402"
C9 C10: "CAP, CERM, 0.22 µF, 50 V, +/- 10%, X7R, 0603"
C11: "CAP, CERM, 0.47uF, 6.3V, +/-10%, X7R, 0603"
C12 C14 C16: "CAP, CERM, 0.1uF, 6.3V, +/-10%, X7R, 0402"
C13 C15 C17 C24: "CAP, CERM, 10uF, 6.3V, +/-20%, X5R, 0402"
C19: "CAP, CERM, 7 pF, 50 V, +/- 7%, C0G/NP0, 0805"
C20 C21: "CAP, CERM, 22 pF, 50 V, +/- 5%, C0G/NP0, 0402"
C22: "CAP, CERM, 10 µF, 10 V, +/- 10%, X7R, 0805"
C25: "CAP, CERM, 0.01 µF, 16 V, +/- 10%, X7R, 0603"
D1 D2: "Diode, Schottky, 40V, 0.5A, SOD-123"
D3 D4: "LED, Green, SMD"
D5: "LED, Super Red, SMD"
FID1 FID2 FID3: "Fiducial mark.  There is nothing to buy or mount."
J1 J2 J5 J6 J19: "Header, 100mil, 3x1, Tin plated, TH"
J3 J7 J14 J15 J16 J17 J18 J22 J23 J24 J25: "Jumper Wire, 100mil spacing, pkg of 200, TH"
J4: "TERMINAL BLOCK 5.08MM VERT 2POS, TH"
J8 J9: "Connector, Receptacle, 100mil, 10x2, Gold plated, TH"
J10 J11 J12 J13: "Header, 100mil, 1x1, Tin, TH"
J20: "Header (shrouded), 100 mil, 7x2, Gold plated, TH"
J21: "Connector, TH, SMA"
L1: "Inductor, Shielded Drum Core, Ferrite, 10 µH, 1.4 A, 0.13 ohm, SMD"
L2: "Inductor, Shielded, Ferrite, 10uH, 0.4A, 1.38 ohm, SMD"
Logo1: library part TI_Logo, "Texas Instrument Corporate Signature"
Logo2: library part ESD_Susceptible, "ESD Susceptible Symbol"
Q1: library part "MMBT3904LT1G, ON Semiconductor", "Transistor, NPN, 40 V, 0.2 A, SOT-23"
R1: "RES, 1.6, 5%, 0.125 W, 0805"
R2: "RES, 560 k, 1%, 0.1 W, 0603"
R3: "RES, 2.4 k, 5%, 0.1 W, 0603"
R4: "RES, 54.2 k, 0.5%, 0.1 W, 0603"
R5: "RES, 1.0k ohm, 5%, 0.063W, 0402"
R6 R7 R8: "RES, 10.0 k, 1%, 0.1 W, 0603"
R9: "RES, 100 k, 1%, 0.1 W, 0603"
R10 R11 R12 R17: "RES, 10.0 ohm, 1%, 0.1W, 0603"
R13: "RES, 1.50 k, 1%, 0.1 W, 0603"
R14: "RES, 3.9 k, 5%, 0.1 W, 0603"
R15: "RES, 499 k, 1%, 0.1 W, 0603"
R16: "RES, 47k ohm, 5%, 0.063W, 0402"
R18 R19: "RES, 1.00 M, 1%, 0.1 W, 0603"
R20: "RES, 560, 5%, 0.1 W, 0603"
S1: "Switch, Push Button, SMD"
SH-J1 SH-J2 SH-J5 SH-J6 SH-J19: "Shunt, 100mil, Gold plated, Black"
TP1: "Test Point, Miniature, White, TH"
TP2 TP7: "Test Point, Miniature, Black, TH"
TP3 TP4 TP5 TP6: "Test Point, Miniature, Red, TH"
U1: "28-V Output Voltage Boost Converter, YFF0006AAAA"
U2: "Single Output High PSRR LDO, 150 mA, Fixed 3.3 V Output, 2.5 to 6.5 V Input, with Low IQ, 5-pin SC70 (DCK), -40 to 85 degC, Green (RoHS & no Sb/Br)"
U3: "CMOS Hex Buffer/Converters, D0016A"
U4: "Mixed Signal Microcontroller, RSB0040B"
U5: "1.8V Precison, Single Low Noise CMOS Input Op Amp, DBV0005A"
Y1: "Crystal, 40kHz, 12.5pF, SMD"
ZZ1: library part AssemblyNoteLabel
ZZ2 ZZ3 ZZ4: library part AssemblyNote

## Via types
v1: diameter 32, hole 16, Top Layer to Bottom Layer, tented both sides, 60 vias
v2: diameter 24, hole 12, Top Layer to Bottom Layer, tented both sides, 11 vias
v3: diameter 19.68, hole 7.87, Top Layer to Bottom Layer, tented both sides, 5 vias

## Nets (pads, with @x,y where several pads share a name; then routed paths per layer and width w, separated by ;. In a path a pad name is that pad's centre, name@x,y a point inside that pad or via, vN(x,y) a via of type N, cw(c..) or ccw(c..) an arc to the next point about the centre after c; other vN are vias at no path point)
+3.3V: J6.2 J7.2 J19.2 R10.2 R11.2 R12.2 R16.2 R17.2 R18.2 | length 435.4
  Top Layer w20: v1(1177.5,1433.5) R10.2@1177.5,1385 v1(1226,1385) ; R12.2@1236.5,730 v1(1285,730) ; v1(1261.5,481.5) R17.2@1325,481.5 v1(1325,545) ; v1(1440,1210) 1441.5,1208.5 R11.2@1441.5,1160 ; v1(1550,575) R18.2@1618.5,575 ; v1(1678,1479) 1679,1480 R16.2@1721.38,1480
  other v1: 1560,1640 1620,1640 1670,1680 1560,1720 1620,1720 1715,1720 1670,1765 1755,1765 1715,1810
+3.3V_LDO: C5.1 J6.1 U2.5 | length 264
  Top Layer w15: U2.5@1580.59,2062.6 1580.59,1975.91 C5.1@1581.5,1975
  Top Layer w40: C5.1@1581.5,1975 1581.5,1802.5 J6.1@1584,1800
+3.3V_LP: J1.1 J6.3 J8.1 | length 1682.4
  Top Layer w40: J1.1@200,1550 200,1785 259,1844 1236,1844 1280,1800 J6.3@1384,1800
  Bottom Layer w40: J1.1@200,1550 200,1492 250,1442 J8.1@250,1350
+5V_LP: J1.3 J2.3 J8.2 | length 1070.7
  Bottom Layer w45: J8.2@350,1350 350,1437 400,1487 J1.3@400,1550 J2.3@400,2400
BSL_RX: J20.14 U4.35 | length 1793.3
  Top Layer w7.87: U4.35@1157.87,1116.46 1157.87,1191.55 1191.33,1225 1240.46,1225 1310,1294.54 1310,1500.75 v2(1324.63,1515.37)
  Bottom Layer w7.87: v2(1324.63,1515.37) 1310,1530 1310,1865 1464.25,2019.25 1719.25,2019.25 J20.14@2050,2350
BSL_TX: J20.12 U4.36 | length 2082.6
  Top Layer w7.87: U4.36@1142.13,1116.46 1142.13,1198.07 1184.8,1240.75 1233.93,1240.75 1290,1296.81 1290,1500 v2(1275,1515)
  Bottom Layer w7.87: v2(1275,1515) 1289.63,1529.63 1289.63,1866.9 1457.73,2035 1712.73,2035 1990,2312.27 1990,2380 2010,2400 2080,2400 2100,2380 2100,2300 J20.12@2050,2250
COM_INV: J23.1 U4.22 | length 1283.4
  Top Layer w7.87: U4.22@1246.46,964.88 1534.88,964.88 1550,980 1550,1150 1600,1200 1690,1200 1740,1150 1740,1100 1790,1050 1850,1050 1900,1100 2150,1100 J23.1@2200,1150
COMPIN: C19.2 R15.1 TP5.1 U4.34 U5.1 | length 1478.6
  Top Layer w7.87: 1173.62,1102.06 U4.34@1173.62,1116.46 1173.62,1173.62 v2(1200,1200)
  Top Layer w15: TP5.1@1650,1100 1690,1060 C19.2@1690,975 R15.1@1690,883.5 ; R15.1@1681.5,875 1825,731.5 1825,430 1807.6,412.6 U5.1@1697.24,412.6
  Bottom Layer w7.87: v2(1200,1200) 1240,1160 1600,1160 1650,1110 TP5.1@1650,1100
EXT_PWR: D2.2 J2.1 J4.1 | length 266.6
  Bottom Layer w45: J4.1@160,2150 160,2245 200,2285 J2.1@200,2400
FB: J5.2 U1.B1 | length 142.1
  Top Layer w7.87: 950,2021 U1.B1@950,2092.13
  Top Layer w15: J5.2@950,1950 950,2021
GND: C1.2 C2.2 C3.2 C4.2 C5.2 C6.2 C7.2 C8.2 C11.2 C12.2 C13.2 C14.2 C15.2 C16.2 C17.2 C18.2 C20.2 C21.2 C22.2 C23.2 C24.2 D3.1 D4.1 D5.1 J4.2 J8.4 J9.2 J13.1 J20.9 J21.2 J21.3 J21.4 J21.5 Q1.2 R4.1 R8.2 R14.1 R19.1 S1.2 TP2.1 TP7.1 U1.A2 U2.2 U3.8 U4.18 U4.26 U4.40 U4.41 U5.2 | length 4549.7
  Top Layer w7.87: v1(890,2125) 917.13,2125 U1.A2@934.19,2107.94 ; v1@1041,1147 1062,1147 1079.13,1129.87 U4.40@1079.13,1116.46 1079.13,1090.87 v3(1150,1020) 1189.37,980.63 U4.18@1189.37,923.54 ; U4.41@1157.87,1027.87 U4.26@1246.46,1027.87
  Top Layer w8: v1(1038,1144) v1@1041,1147 ; v3(1150,1020) U4.41@1157.87,1027.87
  Top Layer w15: C12.2@1155,1270 v1(1200,1270) ; v1(1365,2065) C7.2@1406.38,2065 v1(1406.38,2106.38) ; C4.2@1533.38,2223 1533.38,2195.62 1555,2174 U2.2@1555,2137.4
  Top Layer w20: v1(465,410) 495,440 U3.8@542.72,440 ; v1(670,1140) S1.2@717.32,1140 ; v1(795,863) R8.2@856.5,863 856.6,862.91 Q1.2@856.6,784.24 ; C20.2@920,1673.62 v1(920,1725) ; v1(1014,2389) D3.1@1078.5,2389 ; C13.2@1162.62,1325 v1(1219,1325) ; C16.2@1215.65,850 v1(1272.03,850) ; C21.2@1220,1673.62 v1(1220,1725) ; C17.2@1220.62,796 v1(1277,796) ; R4.1@1255.32,2013.5 1307.5,2013.5 v1(1308,2013) ; C14.2@1430,1050 v1(1490,1050) ; C15.2@1433.62,1100 v1(1490,1100) ; C11.2@1440,1000 v1(1490,1000) ; v1(1464,2300) C3.2@1518.5,2300 ; v1(1485,2223) C4.2@1533.38,2223 ; v1(1550,800) C23.2@1626.38,800 C22.2@1626.38,728.94 ; U5.2@1697.24,450 v1(1775,450) ; D4.1@1770.5,1550 v1(1835,1550) ; v1(1800,1110) D5.1@1800,1178.5
  Top Layer w25: v1(673.62,918.62) C8.2@673.62,875 v1(717.24,875) ; J21.3@800,1550 J21.2@800,1750 J21.5@600,1750 J21.4@600,1550 600,1542 730,1412 730,1278 776,1232 927.38,1232 1015.38,1144 v1(1038,1144) ; C24.2@1400,473.62 v1(1400,525) ; v1(1470,1975) C5.2@1518.5,1975 v1(1518.5,1926.5) ; C18.2@1475,473.62 v1(1475,525) ; v1(1550,175) R14.1@1618.5,175 ; v1(1550,725) C22.2@1614.57,725 ; R19.1@1618.5,650 C22.2@1618.5,721.06
  Bottom Layer w25: J21.4@600,1550 J21.3@800,1550 J21.2@800,1750 J21.5@600,1750 J21.4@600,1550
  other v1: 850,2125 1030,2305 1095,2305 1150,2305
  other v3: 1150,960.94 1090.94,1020 1209.06,1020 1150,1079.06
LCD_EN: J24.2 U4.13 | length 1312.6
  Top Layer w7.87: v2@1050,750 1110.63,810.63 U4.13@1110.63,923.54
  Bottom Layer w7.87: J24.2@100,1050 150,1000 420,1000 484.25,935.75 484.25,865.75 599.36,750.64 v2(1048.91,750.64)
LCD_PWR_CNTL: J22.2 U4.12 | length 1510.6
  Top Layer w7.87: v2@1050,800 1094.88,844.88 U4.12@1094.88,923.54
  Bottom Layer w7.87: J22.2@100,1350 150,1300 400,1300 500,1200 500,872.27 571.63,800.64 v2(1048.91,800.64)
